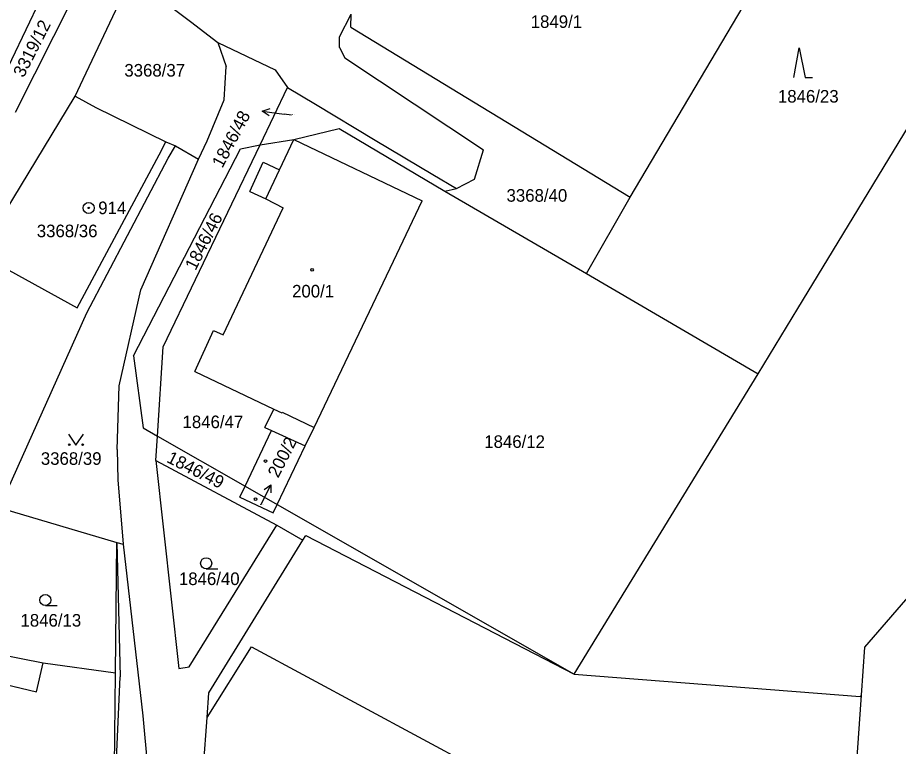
# Model space of a CAD drawing. Extents: x -763205 to -760228, y -1155311 to -1152844.
# Drawn here: x -762035.4 to -761916.2, y -1155049.6 to -1154951 of the extents above; entities that cross this region are included whole.
import ezdxf

# ---------------------------------------------------------------- set-up
doc = ezdxf.new("R2010")
doc.units = 0
for name, color, linetype in [('Vrstva 1', 7, 'Continuous'), ('Vrstva 16', 7, 'Continuous'), ('Vrstva 17', 7, 'Continuous'), ('Vrstva 18', 7, 'Continuous'), ('Vrstva 19', 7, 'Continuous'), ('Vrstva 24', 7, 'Continuous'), ('Vrstva 25', 7, 'Continuous'), ('Vrstva 4', 7, 'Continuous'), ('Vrstva 6', 7, 'Continuous')]:
    doc.layers.add(name, color=color, linetype=linetype)

msp = doc.modelspace()

# ---------------------------------------------------------------- linework, layer by layer
at = {"layer": 'Vrstva 1'}
for p, q in [((-761929.86, -1154990.35), (-761899.65, -1154940.66)), ((-761952.53, -1154975.27), (-761934.04, -1154944.1)), ((-762026.56, -1154959.32), (-762020.76, -1154947.08)), ((-762038.91, -1154962.25), (-762032.34, -1154948.5)), ((-762016.73, -1154947.97), (-762012.05, -1154951.51)), ((-761991.85, -1154953.58), (-761990.28, -1154950.52)), ((-761990.32, -1154952.28), (-761990.28, -1154950.52)), ((-762012.05, -1154951.51), (-762008.32, -1154954.34)), ((-761990.32, -1154952.28), (-761952.53, -1154975.27)), ((-762008.32, -1154954.34), (-762000.57, -1154958.06)), ((-762008.32, -1154954.34), (-762007.2, -1154957.58)), ((-761991.87, -1154955.04), (-761991.85, -1154953.58)), ((-761991.87, -1154955.04), (-761991.16, -1154956.45)), ((-761991.16, -1154956.45), (-761972.4, -1154968.89)), ((-762007.46, -1154962.11), (-762007.2, -1154957.58)), ((-762000.57, -1154958.06), (-761998.89, -1154960.46)), ((-762027.64, -1154961.63), (-762026.56, -1154959.32)), ((-762002.6, -1154968.19), (-761998.89, -1154960.46)), ((-761998.89, -1154960.46), (-761995.13, -1154962.71)), ((-762037.09, -1154977.24), (-762027.64, -1154961.63)), ((-762027.64, -1154961.63), (-762024.84, -1154963.14)), ((-762009.78, -1154967.67), (-762007.46, -1154962.11)), ((-761995.13, -1154962.71), (-761987.03, -1154967.55)), ((-762024.84, -1154963.14), (-762015.36, -1154967.81)), ((-762010.95, -1154970.15), (-762009.78, -1154967.67)), ((-761999.98, -1154971.58), (-761998.03, -1154967.49)), ((-761998.03, -1154967.49), (-761980.68, -1154975.76)), ((-761987.03, -1154967.55), (-761979.22, -1154972.22)), ((-762016.28, -1154969.54), (-762015.36, -1154967.81)), ((-762015.73, -1154995.54), (-762002.6, -1154968.19)), ((-762015.36, -1154967.81), (-762014.06, -1154968.31)), ((-762015.04, -1154970.01), (-762014.06, -1154968.31)), ((-762014.06, -1154968.31), (-762010.95, -1154970.15)), ((-761973.59, -1154972.83), (-761972.4, -1154968.89)), ((-762027.35, -1154990.25), (-762016.28, -1154969.54)), ((-762026.08, -1154990.94), (-762015.04, -1154970.01)), ((-762018.76, -1154987.79), (-762010.95, -1154970.15)), ((-762004, -1154974.49), (-762002.2, -1154970.52)), ((-762002.2, -1154970.52), (-761999.98, -1154971.58)), ((-761979.22, -1154972.22), (-761976.05, -1154974.1)), ((-761976.05, -1154974.1), (-761973.59, -1154972.83)), ((-762004, -1154974.49), (-762001.85, -1154975.51)), ((-761977.61, -1154974.48), (-761976.05, -1154974.1)), ((-761977.61, -1154974.48), (-761958.44, -1154985.62)), ((-762001.85, -1154975.51), (-761999.48, -1154976.7)), ((-761984.56, -1154983.94), (-761980.68, -1154975.76)), ((-761958.44, -1154985.62), (-761952.53, -1154975.27)), ((-762007.59, -1154993.91), (-761999.48, -1154976.7)), ((-762037.95, -1154984.44), (-762027.35, -1154990.25)), ((-761995.31, -1155006.42), (-761984.56, -1154983.94)), ((-761958.44, -1154985.62), (-761935.23, -1154999.17)), ((-762021.7, -1155000.8), (-762018.76, -1154987.79)), ((-761935.23, -1154999.17), (-761929.86, -1154990.35)), ((-762037.48, -1155016.39), (-762026.08, -1154990.94)), ((-762011.44, -1154998.85), (-762008.91, -1154993.31)), ((-762008.91, -1154993.31), (-762007.59, -1154993.91)), ((-762016.5, -1155007.59), (-762015.73, -1154995.54)), ((-762011.44, -1154998.85), (-762000.75, -1155003.94)), ((-761960.09, -1155039.78), (-761935.23, -1154999.17)), ((-762021.96, -1155009.42), (-762021.7, -1155000.8)), ((-762001.95, -1155006.45), (-762000.75, -1155003.94)), ((-762004.65, -1155014.35), (-762001.06, -1155006.85)), ((-762001.95, -1155006.45), (-762001.06, -1155006.85)), ((-761996.5, -1155008.91), (-761995.31, -1155006.42)), ((-762016.71, -1155010.91), (-762016.5, -1155007.59)), ((-762021.96, -1155009.42), (-762021.85, -1155013.52)), ((-762000.29, -1155016.84), (-761996.5, -1155008.91)), ((-762016.71, -1155010.91), (-762013.59, -1155039.05)), ((-762016.71, -1155010.91), (-762000.33, -1155019.65)), ((-762021.85, -1155013.52), (-762021.13, -1155022.19)), ((-762005.37, -1155015.86), (-762004.65, -1155014.35)), ((-762005.37, -1155015.86), (-762000.82, -1155017.96)), ((-762037.52, -1155017.38), (-762022.02, -1155021.99)), ((-762000.82, -1155017.96), (-762000.29, -1155016.84)), ((-762012.23, -1155038.82), (-762000.33, -1155019.65)), ((-762000.33, -1155019.65), (-761996.82, -1155021.69)), ((-761920.79, -1155036.16), (-761906.26, -1155019.32)), ((-761996.82, -1155021.69), (-761996.43, -1155021.06)), ((-761996.43, -1155021.06), (-761960.09, -1155039.78)), ((-762022.2, -1155039.62), (-762022.02, -1155021.99)), ((-762022.02, -1155021.99), (-762021.13, -1155022.19)), ((-762021.13, -1155022.19), (-762018.49, -1155045.44)), ((-762009.53, -1155042.33), (-761996.82, -1155021.69)), ((-761921.23, -1155042.62), (-761920.79, -1155036.16)), ((-762038.49, -1155036.96), (-762031.98, -1155038.26)), ((-762031.98, -1155038.26), (-762022.2, -1155039.62)), ((-762013.59, -1155039.05), (-762012.23, -1155038.82)), ((-762022.38, -1155058.04), (-762022.2, -1155039.62)), ((-761960.09, -1155039.78), (-761921.39, -1155042.82)), ((-762009.77, -1155045.65), (-762009.53, -1155042.33)), ((-761921.9, -1155052.36), (-761921.23, -1155042.62)), ((-761921.39, -1155042.82), (-761921.23, -1155042.62)), ((-762018.49, -1155045.44), (-762017.4, -1155057.43)), ((-762011.35, -1155067.44), (-762009.77, -1155045.65))]:
    msp.add_line(p, q, dxfattribs=at)
at = {"layer": 'Vrstva 16'}
for p, q in [((-762002.314, -1154963.653), (-761999.34, -1154964.05)), ((-761998.34, -1154964.18), (-761999.34, -1154964.05)), ((-762001.152, -1155014.165), (-762002.49, -1155016.85)), ((-762002.5, -1155016.88), (-762002.49, -1155016.85))]:
    msp.add_line(p, q, dxfattribs=at)
for points in [[(-762001.389, -1154964.281), (-762002.314, -1154963.653), (-762001.256, -1154963.29)], [(-762002.046, -1155014.837), (-762001.152, -1155014.165), (-762001.151, -1155015.283)]]:
    msp.add_lwpolyline(points, dxfattribs=at)
at = {"layer": 'Vrstva 24'}
for radius in [0.75, 0.1]:
    msp.add_circle((-762025.8, -1154976.73), radius, dxfattribs=at)
at = {"layer": 'Vrstva 25'}
for p, q in [((-762028.53, -1155007.31), (-762027.53, -1155008.81)), ((-762027.53, -1155008.81), (-762026.53, -1155007.31)), ((-762009.91, -1155025.54), (-762008.31, -1155025.54)), ((-762031.67, -1155030.52), (-762030.07, -1155030.52))]:
    msp.add_line(p, q, dxfattribs=at)
msp.add_lwpolyline([(-761930.37, -1154959.08), (-761929.67, -1154955.08), (-761928.87, -1154959.08), (-761927.87, -1154959.08)], dxfattribs=at)
for centre, radius in [((-761995.58, -1154985.11), 0.175), ((-762028.43, -1155008.76), 0.112), ((-762026.63, -1155008.76), 0.112), ((-762001.89, -1155010.97), 0.175), ((-762003.22, -1155016.12), 0.175), ((-762009.91, -1155024.79), 0.75), ((-762031.67, -1155029.77), 0.75)]:
    msp.add_circle(centre, radius, dxfattribs=at)
at = {"layer": 'Vrstva 4'}
for p, q in [((-762001.85, -1154975.51), (-761999.98, -1154971.58)), ((-762000.75, -1155003.94), (-761999.66, -1155004.46)), ((-761999.66, -1155004.46), (-761999.61, -1155004.37)), ((-761999.61, -1155004.37), (-761995.31, -1155006.42)), ((-762001.06, -1155006.85), (-761996.5, -1155008.91)), ((-762022.02, -1155021.99), (-762021.54, -1155040.17)), ((-762032.88, -1155042.17), (-762031.98, -1155038.26)), ((-762022.38, -1155058.04), (-762021.54, -1155040.17)), ((-762039.84, -1155040.55), (-762032.88, -1155042.17))]:
    msp.add_line(p, q, dxfattribs=at)
at = {"layer": 'Vrstva 6'}
for p, q in [((-762035.71, -1154963.79), (-762020.47, -1154933.5)), ((-761998.03, -1154967.49), (-761991.9, -1154965.98)), ((-761991.9, -1154965.98), (-761977.61, -1154974.48)), ((-762002.6, -1154968.19), (-761998.03, -1154967.49)), ((-762019.76, -1154996.73), (-762005.26, -1154968.74)), ((-762005.26, -1154968.74), (-762002.6, -1154968.19)), ((-762019.76, -1154996.73), (-762018.42, -1155006.49)), ((-762018.42, -1155006.49), (-762016.5, -1155007.59)), ((-762016.5, -1155007.59), (-762004.65, -1155014.35)), ((-762004.65, -1155014.35), (-762000.29, -1155016.84)), ((-762000.29, -1155016.84), (-761960.09, -1155039.78)), ((-762009.77, -1155045.65), (-762003.79, -1155036.09)), ((-762003.79, -1155036.09), (-761968.09, -1155055.28))]:
    msp.add_line(p, q, dxfattribs=at)

# ---------------------------------------------------------------- texts
at = {"layer": 'Vrstva 16'}
for s, rotation, p in [('1846/48', 62.05133, (-762007.72, -1154971.429)), ('200/2', 62.96806, (-762000.162, -1155013.349))]:
    msp.add_text(s, height=1.7, rotation=rotation, dxfattribs=at).set_placement(p)
at = {"layer": 'Vrstva 17'}
msp.add_text('914', height=1.7, dxfattribs=at).set_placement((-762024.513, -1154977.57))
at = {"layer": 'Vrstva 18'}
for s, height, p in [('1849/1', 1.7, (-761965.987, -1154952.38)), ('3368/37', 1.7, (-762020.983, -1154958.96)), ('1846/23', 1.7, (-761932.537, -1154962.48)), ('1846/48', 0.1, (-761998.317, -1154964.18)), ('3368/40', 1.7, (-761969.263, -1154975.89)), ('3368/36', 1.7, (-762032.833, -1154980.69)), ('1846/47', 1.7, (-762013.107, -1155006.52)), ('1846/12', 1.7, (-761972.277, -1155009.19)), ('3368/39', 1.7, (-762032.283, -1155011.48)), ('1846/40', 1.7, (-762013.597, -1155027.74)), ('1846/13', 1.7, (-762035.037, -1155033.36))]:
    msp.add_text(s, height=height, dxfattribs=at).set_placement(p)
for s, rotation, p in [('3319/12', 62.96806, (-762034.612, -1154959.199)), ('1846/46', 63.02536, (-762011.352, -1154985.29)), ('1846/49', 333.34684, (-762015.379, -1155011.066))]:
    msp.add_text(s, height=1.7, rotation=rotation, dxfattribs=at).set_placement(p)
at = {"layer": 'Vrstva 19'}
for s, height, p in [('200/1', 1.7, (-761998.283, -1154988.84)), ('200/2', 0.1, (-762002.486, -1155016.88))]:
    msp.add_text(s, height=height, dxfattribs=at).set_placement(p)

doc.saveas('drawing.dxf')
